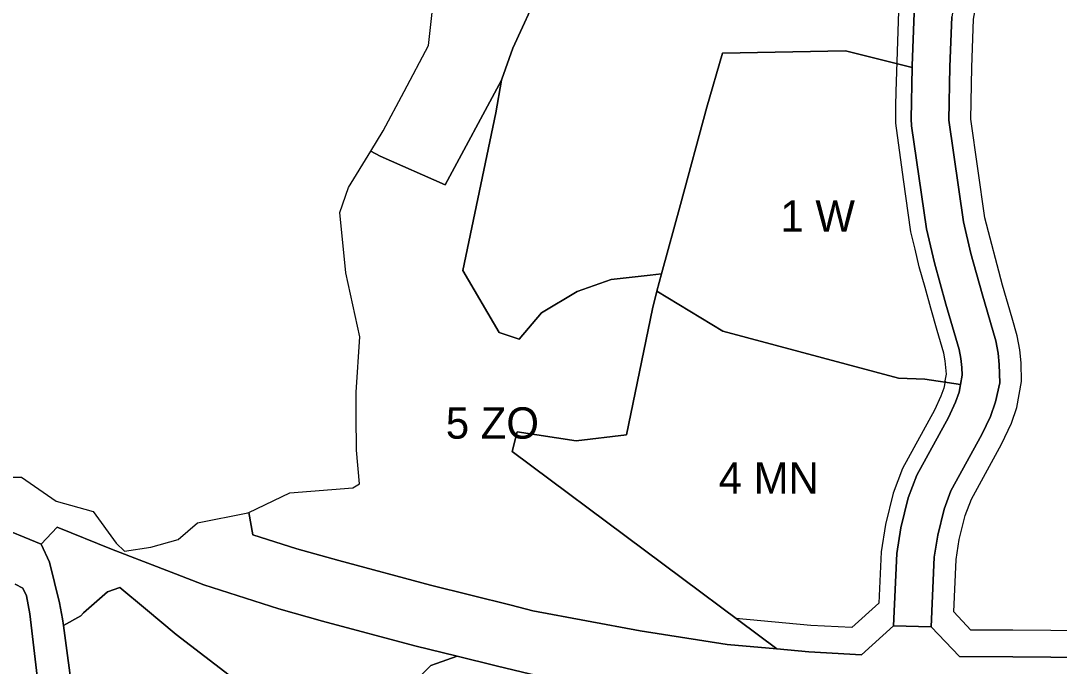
# Model space of a CAD drawing. Extents: x 7424258 to 7426021, y 5551671 to 5553193.
# Drawn here: x 7424679.4 to 7425010.8, y 5552048.8 to 5552254.6 of the extents above; entities that cross this region are included whole.
import ezdxf

# ---------------------------------------------------------------- set-up
doc = ezdxf.new("R2010")
doc.units = 0
for name, color, linetype in [('linie_rozgraniczajace', 7, 'Continuous'), ('linie_zabudowy_nieprzekraczalne', 7, 'Continuous'), ('oznaczenia_przeznaczen', 7, 'Continuous')]:
    doc.layers.add(name, color=color, linetype=linetype)

msp = doc.modelspace()

# ---------------------------------------------------------------- linework, layer by layer
at = {"layer": 'linie_rozgraniczajace'}
for points in [[(7425012.96, 5552360.1), (7424997.27, 5552325.91), (7424986.41, 5552297.84), (7424979.6, 5552273.17), (7424976.55, 5552255.92), (7424975.95, 5552239.91), (7424975.57, 5552222.89), (7424980.24, 5552190.48), (7424982.64, 5552180.39), (7424986.2, 5552167.56), (7424990.59, 5552152.55), (7424991.3, 5552148.61), (7424991.71, 5552144.98), (7424991.83, 5552139.15), (7424990.47, 5552133.05), (7424988.85, 5552128.42), (7424986.17, 5552122.7), (7424976.29, 5552104.66), (7424974.12, 5552098.87), (7424972.08, 5552090.57), (7424970.97, 5552083.52), (7424969.97, 5552061.31), (7424957.97, 5552061.6)], [(7424853.66, 5552283.41), (7424836.47, 5552245.91), (7424832.92, 5552235.98), (7424832.88, 5552235.72), (7424814.91, 5552202.27), (7424794.09, 5552211.49), (7424791.12, 5552213.07), (7424795.09, 5552219.56), (7424801.81, 5552232.03), (7424809.54, 5552246.79), (7424810.92, 5552259.2)], [(7424964.59, 5552257.19), (7424963.95, 5552240.26), (7424963.95, 5552239.73), (7424942.61, 5552245), (7424903.42, 5552244.3), (7424898.36, 5552227.1), (7424889.93, 5552195.99), (7424883.94, 5552173.86), (7424880.29, 5552173.52), (7424867.82, 5552172.09), (7424856.98, 5552168.3), (7424845.66, 5552161.44), (7424838.45, 5552153.05), (7424832.14, 5552155.23), (7424820.56, 5552175.01), (7424830.99, 5552225.27), (7424832.88, 5552235.72), (7424832.92, 5552235.98), (7424836.47, 5552245.91), (7424853.66, 5552283.41)], [(7424957.97, 5552061.6), (7424959.01, 5552084.73), (7424960.31, 5552092.94), (7424962.62, 5552102.42), (7424965.36, 5552109.68), (7424975.46, 5552128.13), (7424977.73, 5552132.96), (7424978.86, 5552136.18), (7424979.32, 5552138.59), (7424979.87, 5552141.54), (7424979.75, 5552144), (7424979.42, 5552146.86), (7424978.89, 5552149.79), (7424974.66, 5552164.28), (7424971.02, 5552177.39), (7424968.44, 5552188.23), (7424963.69, 5552221.14), (7424963.57, 5552223.39), (7424963.95, 5552239.73), (7424963.95, 5552240.26), (7424964.59, 5552257.19)], [(7425032.48, 5552051.43), (7424996.02, 5552051.74), (7424979.01, 5552051.81), (7424969.97, 5552061.31), (7424970.97, 5552083.52), (7424972.08, 5552090.57), (7424974.12, 5552098.87), (7424976.29, 5552104.66), (7424986.17, 5552122.7), (7424988.85, 5552128.42), (7424990.47, 5552133.05), (7424991.83, 5552139.15), (7424991.71, 5552144.98), (7424991.3, 5552148.61), (7424990.59, 5552152.55), (7424986.2, 5552167.56), (7424982.64, 5552180.39), (7424980.24, 5552190.48), (7424975.57, 5552222.89), (7424975.95, 5552239.91), (7424976.55, 5552255.92)], [(7424673, 5552109), (7424679.62, 5552109.03), (7424690.76, 5552101.36), (7424702.59, 5552098.1), (7424709.88, 5552088.03), (7424712.54, 5552085.46), (7424720.98, 5552086.7), (7424729.63, 5552089.19), (7424735.79, 5552094.51), (7424751.93, 5552097.69), (7424752.23, 5552097.83), (7424753.47, 5552090.71), (7424767.49, 5552086.21), (7424780.97, 5552082.45), (7424810.19, 5552074.6), (7424835.91, 5552068.27), (7424842.83, 5552066.41), (7424877.12, 5552060), (7424904.89, 5552055.73), (7424920.72, 5552054.25), (7424930.96, 5552053.29), (7424947.75, 5552052.37), (7424957.97, 5552061.6), (7424969.97, 5552061.31), (7424979.01, 5552051.81), (7424996.02, 5552051.74), (7425032.48, 5552051.43)], [(7424670.82, 5552093.85), (7424685.96, 5552087.72), (7424688.62, 5552081.92), (7424691.78, 5552068.94), (7424692.77, 5552063.89), (7424693.04, 5552061.78), (7424693.89, 5552055.37), (7424695.36, 5552045.03)], [(7425032.81, 5552031.43), (7424995.89, 5552031.74), (7424973.91, 5552031.84), (7424955.58, 5552031.92), (7424929.48, 5552033.35), (7424902.43, 5552035.87), (7424879.98, 5552039.33), (7424873.76, 5552040.29), (7424842.16, 5552046.19), (7424831.17, 5552048.83), (7424818.67, 5552051.92), (7424805.2, 5552055.23), (7424775.7, 5552063.16), (7424761.74, 5552067.05), (7424737.86, 5552074.72), (7424728.86, 5552078.21), (7424708.37, 5552086.04), (7424691.05, 5552093.06), (7424685.96, 5552087.72), (7424670.82, 5552093.85)], [(7424750.47, 5552042.38), (7424729, 5552058.86), (7424719.24, 5552067.02), (7424711.08, 5552073.85), (7424707.07, 5552072.52), (7424699.48, 5552065.75), (7424698.61, 5552064.87), (7424693.04, 5552061.78), (7424692.77, 5552063.89), (7424691.78, 5552068.94), (7424688.62, 5552081.92), (7424685.96, 5552087.72), (7424691.05, 5552093.06), (7424708.37, 5552086.04), (7424728.86, 5552078.21), (7424737.86, 5552074.72), (7424761.74, 5552067.05), (7424775.7, 5552063.16), (7424805.2, 5552055.23), (7424818.67, 5552051.92), (7424812.09, 5552049.6), (7424810.34, 5552048.98), (7424803.82, 5552042.57)], [(7424677.62, 5552074.88), (7424680.06, 5552073.64), (7424681.31, 5552071.2), (7424682.38, 5552065.45), (7424684.08, 5552051.04), (7424687.05, 5552025.56), (7424687.96, 5552017.41), (7424688.32, 5552014.2), (7424688.51, 5552011.44), (7424689.18, 5551994.38), (7424690.41, 5551972.83), (7424691.84, 5551950.51), (7424693.07, 5551930.65), (7424696.39, 5551908.08), (7424698.2, 5551895.73), (7424702.85, 5551874.25), (7424706.24, 5551858.3), (7424698.38, 5551859.38), (7424687.92, 5551860.23), (7424590.95, 5551868.06)], [(7424687.05, 5552025.56), (7424684.08, 5552051.04), (7424682.38, 5552065.45), (7424681.31, 5552071.2), (7424680.06, 5552073.64), (7424677.62, 5552074.88)], [(7424695.36, 5552045.03), (7424693.89, 5552055.37), (7424693.04, 5552061.78), (7424698.61, 5552064.87), (7424699.48, 5552065.75), (7424707.07, 5552072.52), (7424711.08, 5552073.85), (7424719.24, 5552067.02), (7424729, 5552058.86), (7424750.47, 5552042.38)], [(7424803.82, 5552042.57), (7424810.34, 5552048.98), (7424812.09, 5552049.6), (7424818.67, 5552051.92), (7424831.17, 5552048.83), (7424842.16, 5552046.19)]]:
    msp.add_lwpolyline(points, dxfattribs=at)
for points in [[(7424882.45, 5552168.36), (7424883.94, 5552173.86), (7424889.93, 5552195.99), (7424898.36, 5552227.1), (7424903.42, 5552244.3), (7424942.61, 5552245), (7424963.95, 5552239.73), (7424963.57, 5552223.39), (7424963.69, 5552221.14), (7424968.44, 5552188.23), (7424971.02, 5552177.39), (7424974.66, 5552164.28), (7424978.89, 5552149.79), (7424979.42, 5552146.86), (7424979.75, 5552144), (7424979.87, 5552141.54), (7424979.32, 5552138.59), (7424967.95, 5552140.28), (7424959.49, 5552140.59), (7424903.52, 5552155.67)], [(7424752.23, 5552097.83), (7424765.27, 5552104.07), (7424785.44, 5552105.61), (7424787.54, 5552106.97), (7424786.62, 5552117.66), (7424786.51, 5552128.62), (7424786.45, 5552136.13), (7424787.64, 5552153.84), (7424783.14, 5552174.2), (7424781.31, 5552193.51), (7424784.07, 5552201.45), (7424791.12, 5552213.07), (7424794.09, 5552211.49), (7424814.91, 5552202.27), (7424832.88, 5552235.72), (7424830.99, 5552225.27), (7424820.56, 5552175.01), (7424832.14, 5552155.23), (7424838.45, 5552153.05), (7424845.66, 5552161.44), (7424856.98, 5552168.3), (7424867.82, 5552172.09), (7424880.29, 5552173.52), (7424883.94, 5552173.86), (7424882.45, 5552168.36), (7424881.02, 5552162.75), (7424872.71, 5552122.53), (7424856.67, 5552120.6), (7424837.86, 5552123.49), (7424836.26, 5552117.2), (7424920.72, 5552054.25), (7424904.89, 5552055.73), (7424877.12, 5552060), (7424842.83, 5552066.41), (7424835.91, 5552068.27), (7424810.19, 5552074.6), (7424780.97, 5552082.45), (7424767.49, 5552086.21), (7424753.47, 5552090.71)], [(7424882.45, 5552168.36), (7424903.52, 5552155.67), (7424959.49, 5552140.59), (7424967.95, 5552140.28), (7424979.32, 5552138.59), (7424978.86, 5552136.18), (7424977.73, 5552132.96), (7424975.46, 5552128.13), (7424965.36, 5552109.68), (7424962.62, 5552102.42), (7424960.31, 5552092.94), (7424959.01, 5552084.73), (7424957.97, 5552061.6), (7424947.75, 5552052.37), (7424930.96, 5552053.29), (7424920.72, 5552054.25), (7424836.26, 5552117.2), (7424837.86, 5552123.49), (7424856.67, 5552120.6), (7424872.71, 5552122.53), (7424881.02, 5552162.75)]]:
    msp.add_lwpolyline(points, close=True, dxfattribs=at)
at = {"layer": 'linie_zabudowy_nieprzekraczalne'}
for points in [[(7424974.35, 5552139.25), (7424974.86, 5552141.92), (7424974.48, 5552146.11), (7424974.02, 5552148.64), (7424971.92, 5552155.83), (7424969.86, 5552162.91), (7424968.01, 5552169.54), (7424966.18, 5552176.15), (7424964.84, 5552181.75), (7424963.52, 5552187.29), (7424961.12, 5552203.96), (7424958.64, 5552222), (7424958.67, 5552227.64), (7424958.77, 5552231.99), (7424959.6, 5552257.72), (7424963, 5552276.92), (7424970.25, 5552303.17), (7424981.6, 5552332.53), (7424997.47, 5552367.09), (7425003.55, 5552381.47), (7425014.43, 5552407.8)], [(7424977.19, 5552066.06), (7424977.94, 5552082.81), (7424978.95, 5552089.19), (7424980.81, 5552096.8), (7424982.8, 5552102.06), (7424992.42, 5552119.53), (7424995.57, 5552126.27), (7424997.25, 5552131.23), (7424998.83, 5552139.52), (7424998.7, 5552145.49), (7424998.23, 5552149.63), (7424997.41, 5552154.15), (7424995.78, 5552159.74), (7424992.71, 5552170.26), (7424987.12, 5552191.79), (7424982.57, 5552223.26), (7424982.95, 5552239.7), (7424983.52, 5552255.17), (7424986.44, 5552271.63), (7424993.06, 5552295.63), (7425003.72, 5552323.19), (7425018.64, 5552355.47)], [(7424974.42, 5552139.64), (7424974.01, 5552137.48), (7424973.09, 5552134.86), (7424971, 5552130.4), (7424960.81, 5552111.77), (7424957.85, 5552103.92), (7424955.41, 5552093.93), (7424954.03, 5552085.24), (7424953.29, 5552068.82), (7424944.68, 5552061.05), (7424931.58, 5552061.77), (7424907.62, 5552064.01)], [(7424977.19, 5552066.06), (7424982.67, 5552060.3)], [(7425032.35, 5552059.93), (7424996.07, 5552060.24), (7424982.67, 5552060.3)]]:
    msp.add_lwpolyline(points, dxfattribs=at)

# ---------------------------------------------------------------- texts
at = {"layer": 'oznaczenia_przeznaczen'}
for s, p in [('1 W', (7424921.87, 5552187.33)), ('5 ZO', (7424815.08, 5552121.33)), ('4 MN', (7424902.17, 5552103.77))]:
    msp.add_text(s, height=10, dxfattribs=at).set_placement(p)

doc.saveas('drawing.dxf')
